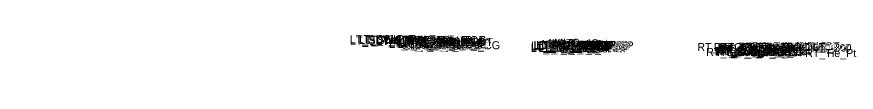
# Model space of a CAD drawing. Extents: x 0 to 4229, y -1 to 9523.
# Drawn here: x 4000 to 4209.8, y 1500 to 1509.8 of the extents above; entities that cross this region are included whole.
import ezdxf

# ---------------------------------------------------------------- set-up
doc = ezdxf.new("R2010")
doc.units = 0
doc.layers.add('Default', color=7, linetype='Continuous')

msp = doc.modelspace()

# ---------------------------------------------------------------- texts
at = {"layer": 'Default'}
for s, height, p in [('LT_SDWK_Out_Top', 2, (4083.24, 1507.71)), ('LT_SDWK_Out_Bot', 2, (4083.27, 1507.38)), ('LT_CSLP_Pnt', 2, (4085.17, 1507.74)), ('LT_Sub_Trench_Out_DLT', 2, (4085.56, 1507.54)), ('LT_Tie_Pt', 2, (4086.95, 1507.57)), ('LT_SDWK_In_Top', 2, (4089.86, 1507.61)), ('LT_SDWK_In_Bot', 2, (4089.89, 1507.28)), ('LT_CG1_Shelf_Out', 2, (4093.05, 1506.52)), ('LT_CG_Top_Face', 2, (4094.76, 1507.5)), ('LT_CG_Top_BOC', 2, (4095.28, 1507.5)), ('LT_CG_Top_Gut', 2, (4095.74, 1507)), ('LT_PV2_OEOT', 2, (4099.67, 1506.78)), ('LT_PV1_OEOT', 2, (4100.24, 1507.03)), ('MI_Top In', 2, (4132.86, 1506.79)), ('MI_Top Out', 2, (4133.72, 1506.7)), ('MI_Crown', 2, (4134.32, 1506.81)), ('LT_CG_Bot_BOC', 2, (4095.31, 1506.51)), ('LT_Sub_OEOP', 2, (4096.37, 1506.27)), ('LT_Sub_OEOT_CG', 2, (4096.87, 1506.2)), ('LT_CG_Bot_IE', 2, (4099.41, 1506.45)), ('LT_Sub_OEOT', 2, (4099.58, 1506.16)), ('LT_PV3_OEOT', 2, (4099.67, 1506.53)), ('LT_Sub_OEEOP', 2, (4128.46, 1505.5)), ('LT_PV2_OEEOP', 2, (4128.56, 1506.12)), ('LT_PV3_OEEOP', 2, (4128.56, 1505.87)), ('LT_PV1_OEEOP', 2, (4129.12, 1506.25)), ('LT_PV2_IEEOP', 2, (4129.2, 1506.12)), ('LT_PV1_IEEOP', 2, (4129.77, 1506.25)), ('LT_PV2_PGL1', 2, (4130.13, 1506.12)), ('LT_PV3_PGL1', 2, (4130.13, 1505.87)), ('LT_PV2_PGL', 2, (4130.46, 1506.12)), ('LT_PV4_PGL', 2, (4130.46, 1505.5)), ('LT_PV1_PGL', 2, (4131.03, 1506.37)), ('MI_Face In', 2, (4131.15, 1506.54)), ('MI_Bot In', 2, (4132.13, 1506.37)), ('RT_Sub_OEEOP', 2, (4132.42, 1505.41)), ('RT_PV2_OEEOP', 2, (4132.51, 1506.03)), ('RT_PV3_OEEOP', 2, (4132.51, 1505.78)), ('RT_PV1_OEEOP', 2, (4133.08, 1506.16)), ('RT_PV2_IEEOP', 2, (4133.16, 1506.03)), ('MI_Face Out', 2, (4133.51, 1506.45)), ('RT_PV1_IEEOP', 2, (4133.72, 1506.16)), ('RT_PV2_PGL1', 2, (4134.08, 1506.03)), ('RT_PV3_PGL1', 2, (4134.08, 1505.78)), ('RT_PV2_PGL', 2, (4134.42, 1506.03)), ('RT_PV4_PGL', 2, (4134.42, 1505.41)), ('MI_Bot Out', 2, (4134.51, 1506.28)), ('RT_PV1_PGL', 2, (4134.98, 1506.28)), ('RT_Sub_Trench_Out_DLT', 2, (4170.1, 1505.77)), ('RT_Sub_OEOT_CG', 2, (4172.32, 1504.52)), ('RT_CG_Top_Face', 2, (4174.21, 1505.73)), ('RT_CG1_Shelf_Out', 2, (4174.5, 1504.71)), ('RT_CG_Bot_IE', 2, (4174.87, 1504.77)), ('RT_Sub_OEOT', 2, (4175.03, 1504.48)), ('RT_PV2_OEOT', 2, (4175.13, 1505.11)), ('RT_PV3_OEOT', 2, (4175.13, 1504.86)), ('RT_CG_Top_Gut', 2, (4175.19, 1505.23)), ('RT_PV1_OEOT', 2, (4175.69, 1505.36)), ('RT_CG_Top_BOC', 2, (4175.74, 1505.73)), ('RT_CG_Bot_BOC', 2, (4175.77, 1504.72)), ('RT_Sub_OEOP', 2, (4178.32, 1504.45)), ('RT_SDWK_In_Top', 2, (4180.31, 1505.84)), ('RT_SDWK_In_Bot', 2, (4180.34, 1505.51)), ('RT_SDWK_Out_Top', 2, (4183.69, 1505.94)), ('RT_SDWK_Out_Bot', 2, (4183.72, 1505.61)), ('RT_Shld_O', 2, (4190.04, 1505.93)), ('CSLP_Pnt', 2, (4192.37, 1505.97)), ('RT_Tie_Pt', 2, (4197.06, 1504.25)), ('-', 0.0001, (4000, 1500)), ('-', 0.0001, (4000, 1500)), ('-', 0.0001, (4000, 1500)), ('-', 0.0001, (4000, 1500)), ('-', 0.0001, (4000, 1500)), ('-', 0.0001, (4000, 1500)), ('-', 0.0001, (4000, 1500))]:
    msp.add_text(s, height=height, dxfattribs=at).set_placement(p)

doc.saveas('drawing.dxf')
